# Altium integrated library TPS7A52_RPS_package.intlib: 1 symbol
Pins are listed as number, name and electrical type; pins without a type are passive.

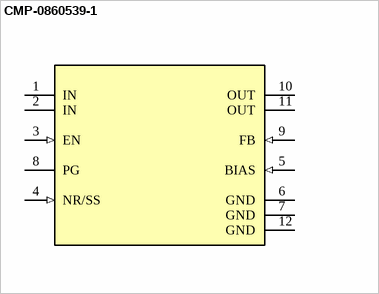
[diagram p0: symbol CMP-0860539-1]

## CMP-0860539-1
designator U?, comment TPS7A5201RPST
3-A, High-Accuracy (0.75%), Low-Noise (4.4μVRMS), LDO Voltage Regulator, RPS0012A (VQFN-12); Alternate Manufacturer: Texas Instruments; SizeZ_mm: 1; SizeX_mm: 2.2; AEC Category: Q200; CompType: IC; SizeAreaWB_mm2: 11.2; SizeY_mm: 2.5; SizeArea_mm2: 5.5; AEC Qualified: N
footprint RPS0012A (VQFN-12)
pins: 1 IN (power), 2 IN (power), 3 EN (in), 4 NR/SS (in), 5 BIAS (in), 6 GND (power), 7 GND (power), 8 PG (oc), 9 FB (in), 10 OUT (power), 11 OUT (power), 12 GND (power)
